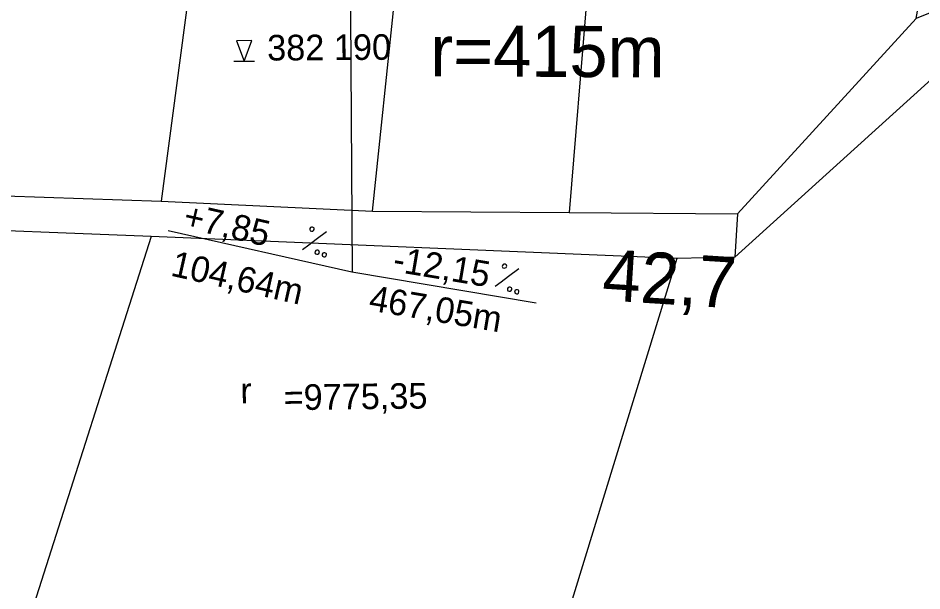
# Model space of a CAD drawing. Extents: x -514509 to -512782, y -1144610 to -1143439.
# Drawn here: x -513195.4 to -513107.2, y -1143679.7 to -1143623.8 of the extents above; entities that cross this region are included whole.
import ezdxf

# ---------------------------------------------------------------- set-up
doc = ezdxf.new("R2010")
doc.units = 0
for name, color, linetype in [('Vrstva 10', 7, 'Continuous'), ('Vrstva 38', 7, 'Continuous'), ('Vrstva 39', 7, 'Continuous'), ('Vrstva 7', 7, 'Continuous'), ('Vrstva 8', 7, 'Continuous')]:
    doc.layers.add(name, color=color, linetype=linetype)

msp = doc.modelspace()

# ---------------------------------------------------------------- linework, layer by layer
at = {"layer": 'Vrstva 10'}
for points in [[(-512782.341, -1143656.666), (-512796.89, -1143661.893), (-512815.309, -1143658.506), (-512846.358, -1143662.813), (-512847.692, -1143673.887), (-512850.552, -1143675.414), (-512874.542, -1143673.507), (-512907.663, -1143668.822), (-512937.442, -1143663.927), (-512942.033, -1143670.511), (-512944.784, -1143662.787), (-512958.978, -1143654.892), (-512977.284, -1143642.016), (-512997.25, -1143628.575), (-513034.474, -1143613.524), (-513050.89, -1143616.331), (-513050.251, -1143607.386), (-513065.331, -1143600.696), (-513084.436, -1143602.206), (-513086.215, -1143618.123), (-513093.877, -1143618.167), (-513107.772, -1143623.787)], [(-512782.341, -1143656.666), (-512796.89, -1143661.893), (-512815.309, -1143658.506), (-512846.358, -1143662.813), (-512847.692, -1143673.887), (-512850.552, -1143675.414), (-512874.542, -1143673.507), (-512907.663, -1143668.822), (-512937.442, -1143663.927), (-512942.033, -1143670.511), (-512944.784, -1143662.787), (-512958.978, -1143654.892), (-512977.284, -1143642.016), (-512997.25, -1143628.575), (-513034.474, -1143613.524), (-513050.89, -1143616.331), (-513050.251, -1143607.386), (-513065.331, -1143600.696), (-513084.436, -1143602.206), (-513086.215, -1143618.123), (-513093.877, -1143618.167), (-513107.772, -1143623.787)], [(-513083.73, -1143602.284), (-513086.215, -1143618.123), (-513093.877, -1143618.167), (-513107.772, -1143623.787), (-513104.437, -1143605.443), (-513156.888, -1143605.053), (-513194.553, -1143607.705), (-513250.415, -1143617.382), (-513252.832, -1143634.619), (-513276.036, -1143634.192), (-513293.984, -1143635.345), (-513297.884, -1143620.719), (-513339.729, -1143642.048), (-513370.62, -1143660.746), (-513392.287, -1143677.542), (-513448.783, -1143734.317), (-513496.135, -1143770.535), (-513525.567, -1143795.084), (-513571.166, -1143828.084), (-513591.968, -1143845.266)], [(-513083.73, -1143602.284), (-513086.215, -1143618.123), (-513093.877, -1143618.167), (-513107.772, -1143623.787), (-513104.437, -1143605.443), (-513156.888, -1143605.053), (-513194.553, -1143607.705), (-513250.415, -1143617.382), (-513252.832, -1143634.619), (-513276.036, -1143634.192), (-513293.984, -1143635.345), (-513297.884, -1143620.719), (-513339.729, -1143642.048), (-513370.62, -1143660.746), (-513392.287, -1143677.542), (-513448.783, -1143734.317), (-513496.135, -1143770.535), (-513525.567, -1143795.084), (-513571.166, -1143828.084), (-513591.968, -1143845.266)]]:
    msp.add_lwpolyline(points, dxfattribs=at)
at = {"layer": 'Vrstva 38'}
for points in [[(-513145.4, -1143593.023), (-513163.146, -1143593.136), (-513162.802, -1143648.559)], [(-513144.838, -1143651.58), (-513162.823, -1143648.563), (-513180.741, -1143644.522)]]:
    msp.add_lwpolyline(points, dxfattribs=at)
at = {"layer": 'Vrstva 39'}
msp.add_line((-513174.323, -1143627.971), (-513172.324, -1143627.958), dxfattribs=at)
for points in [[(-513174.086, -1143625.969), (-513173.324, -1143627.965), (-513172.586, -1143625.96), (-513174.086, -1143625.969)], [(-513165.295, -1143644.617), (-513166.304, -1143645.378), (-513167.025, -1143645.935), (-513167.624, -1143646.365)], [(-513166.649, -1143644.168), (-513166.753, -1143644.171), (-513166.837, -1143644.192), (-513166.901, -1143644.298), (-513166.914, -1143644.409), (-513166.872, -1143644.514), (-513166.747, -1143644.557), (-513166.639, -1143644.544), (-513166.548, -1143644.499), (-513166.481, -1143644.382), (-513166.494, -1143644.274), (-513166.528, -1143644.224), (-513166.649, -1143644.168)], [(-513166.144, -1143646.423), (-513166.247, -1143646.425), (-513166.347, -1143646.454), (-513166.395, -1143646.553), (-513166.424, -1143646.671), (-513166.368, -1143646.768), (-513166.241, -1143646.811), (-513166.139, -1143646.809), (-513166.042, -1143646.753), (-513165.987, -1143646.632), (-513165.992, -1143646.54), (-513166.022, -1143646.479), (-513166.144, -1143646.423)], [(-513165.448, -1143646.667), (-513165.55, -1143646.669), (-513165.651, -1143646.698), (-513165.698, -1143646.797), (-513165.727, -1143646.915), (-513165.671, -1143647.012), (-513165.545, -1143647.055), (-513165.441, -1143647.053), (-513165.345, -1143646.997), (-513165.291, -1143646.875), (-513165.296, -1143646.783), (-513165.325, -1143646.722), (-513165.448, -1143646.667)], [(-513146.519, -1143648.224), (-513147.528, -1143648.985), (-513148.249, -1143649.542), (-513148.848, -1143649.972)], [(-513147.873, -1143647.775), (-513147.977, -1143647.778), (-513148.061, -1143647.799), (-513148.125, -1143647.905), (-513148.138, -1143648.016), (-513148.096, -1143648.121), (-513147.971, -1143648.164), (-513147.863, -1143648.151), (-513147.772, -1143648.106), (-513147.705, -1143647.989), (-513147.718, -1143647.881), (-513147.752, -1143647.831), (-513147.873, -1143647.775)], [(-513147.368, -1143650.03), (-513147.471, -1143650.032), (-513147.571, -1143650.061), (-513147.619, -1143650.16), (-513147.648, -1143650.278), (-513147.592, -1143650.375), (-513147.465, -1143650.418), (-513147.363, -1143650.416), (-513147.266, -1143650.36), (-513147.211, -1143650.239), (-513147.216, -1143650.147), (-513147.246, -1143650.086), (-513147.368, -1143650.03)], [(-513146.672, -1143650.274), (-513146.774, -1143650.276), (-513146.875, -1143650.305), (-513146.922, -1143650.404), (-513146.951, -1143650.522), (-513146.895, -1143650.619), (-513146.769, -1143650.662), (-513146.665, -1143650.66), (-513146.569, -1143650.604), (-513146.515, -1143650.482), (-513146.52, -1143650.39), (-513146.549, -1143650.329), (-513146.672, -1143650.274)]]:
    msp.add_lwpolyline(points, dxfattribs=at)
at = {"layer": 'Vrstva 8'}
for p, q in [((-513160.798, -1143642.595), (-513156.888, -1143605.053)), ((-513138.552, -1143605.19), (-513141.602, -1143642.722)), ((-513176.744, -1143606.452), (-513181.413, -1143641.631)), ((-513182.381, -1143645.093), (-513211.234, -1143735.382))]:
    msp.add_line(p, q, dxfattribs=at)
for points in [[(-513107.772, -1143623.787), (-513125.201, -1143642.865), (-513125.444, -1143647.101), (-513104.89, -1143628.486), (-513088.843, -1143624.07)], [(-513252.985, -1143640.349), (-513241.498, -1143639.695), (-513236.876, -1143639.756), (-513218.068, -1143640.38), (-513200.481, -1143640.984), (-513181.413, -1143641.631), (-513160.798, -1143642.595), (-513141.602, -1143642.722), (-513125.201, -1143642.865)], [(-513131.126, -1143647.212), (-513182.381, -1143645.093), (-513205.617, -1143644.159), (-513232.261, -1143643.275)], [(-513125.444, -1143647.101), (-513131.126, -1143647.212), (-513157.335, -1143732.682)]]:
    msp.add_lwpolyline(points, dxfattribs=at)

# ---------------------------------------------------------------- texts
at = {"layer": 'Vrstva 39'}
for s, height, rotation, p in [('r=415m', 5, 359.72136, (-513155.168, -1143629.44)), ('382 190', 2.5, 0.36576, (-513171.072, -1143627.903)), ('+7,85', 2.5, 347.29079, (-513179.392, -1143644.21)), ('104,64m', 2.5, 347.29079, (-513180.593, -1143648.883)), ('-12,15', 2.5, 350.47866, (-513158.916, -1143648.463)), ('467,05m', 2.5, 350.47866, (-513161.256, -1143652.28)), ('r', 2.5, 0.67081, (-513173.678, -1143661.374)), ('=9775,35', 2.5, 0.67081, (-513169.463, -1143662.031))]:
    msp.add_text(s, height=height, rotation=rotation, dxfattribs=at).set_placement(p)
at = {"layer": 'Vrstva 7'}
msp.add_text('42,7', height=5, rotation=356.41129, dxfattribs=at).set_placement((-513138.469, -1143651.292))

doc.saveas('drawing.dxf')
